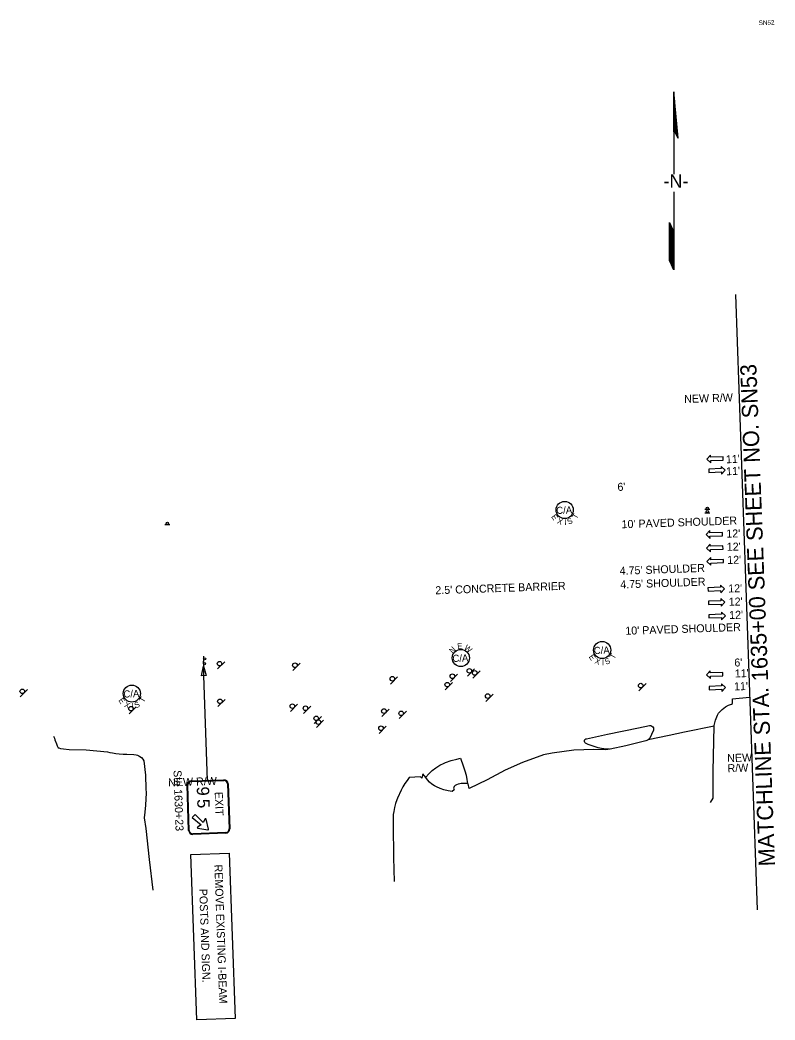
# Model space of a CAD drawing. Extents: x 1808944 to 1810496, y 1189647 to 1190718.
# Drawn here: x 1809835 to 1810496, y 1189721 to 1190596 of the extents above; entities that cross this region are included whole.
import ezdxf

# ---------------------------------------------------------------- set-up
doc = ezdxf.new("R2010")
doc.units = 0
for name, color, linetype in [('RD_EX_Road', 7, 'Continuous'), ('RD_PD_Final_LnLine', 7, 'Continuous'), ('RD_PD_Final_TX', 7, 'Continuous'), ('RD_PD_RW_TX', 7, 'Continuous'), ('RD_SHT_MatchLine', 7, 'Continuous'), ('RD_SHT_TX', 7, 'Continuous'), ('RD_Sketch1', 7, 'Continuous'), ('RD_Sketch10', 7, 'Continuous'), ('RD_Sketch8', 7, 'Continuous'), ('SN_P_Signs', 7, 'Continuous')]:
    doc.layers.add(name, color=color, linetype=linetype)

# ---------------------------------------------------------------- blocks, each defined once
blk = doc.blocks.new('SARRW2')
at = {"layer": 'RD_PD_Final_LnLine'}
blk.add_lwpolyline([(-12, 1.2), (-12, -1.2), (-2.83, -1.2), (-2.83, -2.83), (0, 0), (-2.83, 2.83), (-2.83, 1.2)], close=True, dxfattribs=at)

msp = doc.modelspace()

# ---------------------------------------------------------------- linework, layer by layer
at = {"layer": 'RD_EX_Road'}
for points in [[(1810442.62, 1189977.66), (1810442.64, 1189978.3), (1810443.87, 1189983.17), (1810445.51, 1189987.51), (1810446.58, 1189989.04), (1810449.64, 1189992.5), (1810451.17, 1189993.65), (1810452.54, 1189994.7), (1810455.27, 1189996.17), (1810457.1, 1189996.88), (1810457.92, 1189997.13), (1810458.6, 1189997.63), (1810458.83, 1189998.02), (1810458.65, 1190001.82), (1810473.66, 1190003.13)], [(1810351.07, 1189957.6), (1810348.97, 1189957.54), (1810346.25, 1189957.86), (1810345.56, 1189958), (1810341.05, 1189958.89), (1810336.64, 1189960.16), (1810332.34, 1189961.8), (1810330.14, 1189962.81), (1810329.47, 1189963.43), (1810329.11, 1189964.27), (1810329.14, 1189965.18), (1810329.55, 1189966), (1810330.26, 1189966.57), (1810330.84, 1189966.77), (1810349.43, 1189970.64), (1810376.41, 1189976.27), (1810386.07, 1189978.24), (1810387.15, 1189978.27), (1810388.16, 1189977.91), (1810388.98, 1189977.21), (1810389.5, 1189976.26), (1810389.64, 1189975.19), (1810389.46, 1189974.29), (1810385.99, 1189966.84), (1810384.92, 1189965.82)], [(1810439.35, 1189910.92), (1810441.82, 1189914.89), (1810441.82, 1189938.28), (1810442.62, 1189977.66), (1810416.84, 1189972.42), (1810403.36, 1189969.57), (1810384.91, 1189965.82), (1810383.61, 1189965.13), (1810382.82, 1189964.9), (1810365.42, 1189960.68), (1810351.7, 1189957.62)], [(1809864.47, 1189969.08), (1809865.33, 1189967.42), (1809865.66, 1189965.91), (1809867.01, 1189962.37), (1809867.68, 1189960.69), (1809868.28, 1189959.44), (1809868.64, 1189958.94), (1809869.18, 1189958.73), (1809870.63, 1189958.34), (1809873.18, 1189957.97), (1809878.17, 1189957.45), (1809892.95, 1189957.07), (1809911.79, 1189955.22), (1809913.82, 1189954.81), (1809915.99, 1189954.46), (1809919.13, 1189953.93), (1809921.98, 1189953.48), (1809925.48, 1189953.35), (1809928.56, 1189953.14), (1809934.88, 1189952.99), (1809936.96, 1189952.63), (1809938.09, 1189952.27), (1809939.22, 1189951.71), (1809940.01, 1189951.28), (1809941.45, 1189950.41), (1809942.74, 1189948.86), (1809943.44, 1189947.42), (1809944.99, 1189934.83), (1809945.4, 1189922.89), (1809945.7, 1189919.36), (1809945.12, 1189908.75), (1809944.29, 1189902.53), (1809943.95, 1189897.58), (1809945.27, 1189888.18), (1809948.1, 1189861), (1809951.3, 1189834.39)], [(1810351.7, 1189957.62), (1810347.88, 1189957.19), (1810337.48, 1189957.23), (1810319.88, 1189956.84), (1810301.01, 1189954.22), (1810293.31, 1189952.6), (1810274.9, 1189946.06), (1810259.72, 1189939.2), (1810243.93, 1189930.88), (1810228.37, 1189923.1), (1810227.29, 1189927.42), (1810226.65, 1189927.52)], [(1810190.36, 1189933.03), (1810193.02, 1189936.11), (1810195.97, 1189938.92), (1810199.18, 1189941.43), (1810202.61, 1189943.61), (1810206.24, 1189945.45), (1810207.41, 1189945.95), (1810212.39, 1189947.67), (1810217.49, 1189949.02), (1810220.64, 1189949.64), (1810223.08, 1189942.98), (1810224.45, 1189938.59), (1810225.58, 1189934.85), (1810226.32, 1189931.02), (1810226.65, 1189927.52)], [(1810226.65, 1189927.52), (1810224.01, 1189927.73), (1810221.37, 1189927.54), (1810218.79, 1189926.96), (1810218.57, 1189926.89), (1810217.28, 1189926.58), (1810216.13, 1189925.91), (1810215.22, 1189924.94), (1810214.79, 1189924.15), (1810214.6, 1189923.39), (1810214.8, 1189922.63), (1810215.22, 1189922.14), (1810213.33, 1189920.65), (1810209.74, 1189921.1), (1810206.21, 1189921.94), (1810202.79, 1189923.15), (1810199.52, 1189924.73), (1810197.95, 1189925.66), (1810195.68, 1189927.04), (1810193.63, 1189928.74), (1810191.86, 1189930.72), (1810190.37, 1189932.98), (1810187.61, 1189935.99), (1810186.82, 1189932.14), (1810185.74, 1189933.59), (1810175.86, 1189932.99), (1810173.86, 1189930.31), (1810172.02, 1189927.52), (1810170.34, 1189924.62), (1810168.86, 1189921.67), (1810165.55, 1189914.78), (1810164.93, 1189913.42), (1810163.85, 1189910.06), (1810162.95, 1189906.65), (1810162.25, 1189903.19), (1810161.85, 1189900.48), (1810161.61, 1189891.47), (1810162, 1189862.97), (1810162.47, 1189841.87)]]:
    msp.add_lwpolyline(points, dxfattribs=at)
at = {"layer": 'RD_SHT_MatchLine'}
msp.add_line((1810461.25, 1190355.41), (1810480.22, 1189817.08), dxfattribs=at)
at = {"layer": 'RD_Sketch1'}
for p, q in [((1810407.42, 1190532.83), (1810407.22, 1190497.66)), ((1810411.15, 1190492.12), (1810407.42, 1190532.83)), ((1810407.42, 1190497.96), (1810407.42, 1190476.13)), ((1810407.73, 1190499.07), (1810411.15, 1190492.12)), ((1810407.42, 1190476.13), (1810407.42, 1190460.66)), ((1810407.42, 1190445.21), (1810407.42, 1190419.44)), ((1810403.43, 1190404.38), (1810403.43, 1190418.55)), ((1810403.43, 1190418.55), (1810407.42, 1190409.99)), ((1810407.42, 1190419.44), (1810407.42, 1190376.92)), ((1810403.43, 1190385.48), (1810403.43, 1190404.38)), ((1810407.42, 1190376.92), (1810403.43, 1190385.48))]:
    msp.add_line(p, q, dxfattribs=at)
for points in [[(1810407.44, 1190498.26), (1810407.44, 1190532.7)], [(1810407.53, 1190498.52), (1810407.53, 1190531.67)], [(1810407.62, 1190498.78), (1810407.63, 1190530.64)], [(1810407.72, 1190499.04), (1810407.72, 1190529.61)], [(1810407.81, 1190498.89), (1810407.81, 1190528.57)], [(1810407.91, 1190498.7), (1810407.91, 1190527.54)], [(1810408, 1190498.51), (1810408, 1190526.51)], [(1810407.34, 1190498), (1810407.34, 1190518.79)], [(1810408.1, 1190498.32), (1810408.1, 1190525.48)], [(1810408.19, 1190498.12), (1810408.19, 1190524.44)], [(1810408.29, 1190497.93), (1810408.29, 1190523.41)], [(1810408.38, 1190497.74), (1810408.38, 1190522.38)], [(1810408.48, 1190497.55), (1810408.48, 1190521.35)], [(1810408.57, 1190497.36), (1810408.57, 1190520.31)], [(1810408.66, 1190497.17), (1810408.66, 1190519.28)], [(1810408.76, 1190496.97), (1810408.76, 1190518.25)], [(1810408.85, 1190496.78), (1810408.85, 1190517.22)], [(1810408.95, 1190496.59), (1810408.95, 1190516.18)], [(1810409.04, 1190496.4), (1810409.04, 1190515.15)], [(1810409.14, 1190496.21), (1810409.14, 1190514.12)], [(1810409.23, 1190496.02), (1810409.23, 1190513.09)], [(1810409.33, 1190495.82), (1810409.33, 1190512.05)], [(1810409.42, 1190495.63), (1810409.42, 1190511.02)], [(1810409.51, 1190495.44), (1810409.51, 1190509.99)], [(1810409.61, 1190495.25), (1810409.61, 1190508.96)], [(1810407.25, 1190497.75), (1810407.25, 1190502.89)], [(1810409.7, 1190495.06), (1810409.7, 1190507.92)], [(1810409.8, 1190494.86), (1810409.8, 1190506.89)], [(1810409.89, 1190494.67), (1810409.89, 1190505.86)], [(1810409.99, 1190494.48), (1810409.99, 1190504.83)], [(1810410.08, 1190494.29), (1810410.08, 1190503.79)], [(1810410.18, 1190494.1), (1810410.18, 1190502.76)], [(1810410.27, 1190493.91), (1810410.27, 1190501.73)], [(1810410.37, 1190493.71), (1810410.37, 1190500.7)], [(1810410.46, 1190493.52), (1810410.46, 1190499.66)], [(1810410.55, 1190493.33), (1810410.55, 1190498.63)], [(1810410.65, 1190493.14), (1810410.65, 1190497.6)], [(1810410.74, 1190492.95), (1810410.74, 1190496.57)], [(1810410.84, 1190492.76), (1810410.84, 1190495.53)], [(1810410.93, 1190492.56), (1810410.93, 1190494.5)], [(1810411.03, 1190492.37), (1810411.03, 1190493.47)], [(1810411.12, 1190492.18), (1810411.12, 1190492.44)], [(1810403.51, 1190385.32), (1810403.51, 1190418.39)], [(1810403.6, 1190385.12), (1810403.6, 1190418.19)], [(1810403.7, 1190384.91), (1810403.7, 1190417.98)], [(1810403.79, 1190384.71), (1810403.79, 1190417.78)], [(1810403.89, 1190384.51), (1810403.89, 1190417.58)], [(1810403.98, 1190384.31), (1810403.98, 1190417.38)], [(1810404.08, 1190384.1), (1810404.08, 1190417.17)], [(1810404.17, 1190383.9), (1810404.17, 1190416.97)], [(1810404.26, 1190383.7), (1810404.26, 1190416.77)], [(1810404.36, 1190383.5), (1810404.36, 1190416.57)], [(1810404.45, 1190383.29), (1810404.45, 1190416.36)], [(1810404.55, 1190383.09), (1810404.55, 1190416.16)], [(1810404.64, 1190382.89), (1810404.64, 1190415.96)], [(1810404.74, 1190382.68), (1810404.74, 1190415.76)], [(1810404.83, 1190382.48), (1810404.83, 1190415.55)], [(1810404.93, 1190382.28), (1810404.93, 1190415.35)], [(1810405.02, 1190382.08), (1810405.02, 1190415.15)], [(1810405.11, 1190381.87), (1810405.11, 1190414.94)], [(1810405.21, 1190381.67), (1810405.21, 1190414.74)], [(1810405.3, 1190381.47), (1810405.3, 1190414.54)], [(1810405.4, 1190381.27), (1810405.4, 1190414.34)], [(1810405.49, 1190381.06), (1810405.49, 1190414.13)], [(1810405.59, 1190380.86), (1810405.59, 1190413.93)], [(1810405.68, 1190380.66), (1810405.68, 1190413.73)], [(1810405.78, 1190380.46), (1810405.78, 1190413.53)], [(1810405.87, 1190380.25), (1810405.87, 1190413.32)], [(1810405.97, 1190380.05), (1810405.97, 1190413.12)], [(1810406.06, 1190379.85), (1810406.06, 1190412.92)], [(1810406.15, 1190379.65), (1810406.15, 1190412.72)], [(1810406.25, 1190379.44), (1810406.25, 1190412.51)], [(1810406.34, 1190379.24), (1810406.34, 1190412.31)], [(1810406.44, 1190379.04), (1810406.44, 1190412.11)], [(1810406.53, 1190378.83), (1810406.53, 1190411.91)], [(1810406.63, 1190378.63), (1810406.63, 1190411.7)], [(1810406.72, 1190378.43), (1810406.72, 1190411.5)], [(1810406.82, 1190378.23), (1810406.82, 1190411.3)], [(1810406.91, 1190378.02), (1810406.91, 1190411.09)], [(1810407, 1190377.82), (1810407, 1190410.89)], [(1810407.1, 1190377.62), (1810407.1, 1190410.69)], [(1810407.19, 1190377.42), (1810407.19, 1190410.49)], [(1810407.29, 1190377.21), (1810407.29, 1190410.28)], [(1810407.38, 1190377.01), (1810407.38, 1190410.08)]]:
    msp.add_lwpolyline(points, dxfattribs=at)
at = {"layer": 'RD_Sketch10'}
msp.add_circle((1810220.98, 1190037.46), 7.5, dxfattribs=at)
at = {"layer": 'RD_Sketch8'}
for centre in [(1810311.85, 1190166.94), (1810344.68, 1190044.38), (1809933.05, 1190006.29)]:
    msp.add_circle(centre, 7.5, dxfattribs=at)
at = {"layer": 'SN_P_Signs'}
for p, q in [((1810434.43, 1190167.51), (1810438.93, 1190167.51)), ((1810434.39, 1190164.35), (1810438.89, 1190164.35)), ((1809961.89, 1190154.34), (1809966.39, 1190154.34)), ((1809995.6, 1190038.91), (1809995.76, 1190034.42)), ((1809995.54, 1190034.65), (1809995.7, 1190030.16)), ((1809999.22, 1189930.38), (1809995.7, 1190030.16)), ((1810008.04, 1190027.83), (1810014.4, 1190034.19)), ((1810074.01, 1190026.46), (1810080.37, 1190032.83)), ((1810226.67, 1190021.56), (1810233.04, 1190027.93)), ((1810159.27, 1190014.67), (1810165.64, 1190021.03)), ((1810211.82, 1190016.82), (1810218.18, 1190023.18)), ((1810231.39, 1190019.73), (1810237.75, 1190026.09)), ((1810207.3, 1190009.49), (1810213.67, 1190015.85)), ((1810376.64, 1190008.63), (1810383.01, 1190015)), ((1809835.39, 1190003.59), (1809841.75, 1190009.96)), ((1810242.75, 1189999.49), (1810249.11, 1190005.85)), ((1809930.6, 1189988.47), (1809936.96, 1189994.84)), ((1810008.38, 1189994.87), (1810014.74, 1190001.24)), ((1810071.74, 1189990.62), (1810078.1, 1189996.99)), ((1810083.25, 1189988.84), (1810089.61, 1189995.21)), ((1810151.86, 1189986.34), (1810158.23, 1189992.71)), ((1810092.64, 1189980.01), (1810099, 1189986.38)), ((1810166.99, 1189984.41), (1810173.36, 1189990.77)), ((1810094.55, 1189976.75), (1810100.91, 1189983.11)), ((1810149.35, 1189971.34), (1810155.71, 1189977.71)), ((1809982.74, 1189886.57), (1809981.35, 1189926.14)), ((1809983.34, 1189886.59), (1809981.95, 1189926.16)), ((1809984.82, 1189929.87), (1810013.6, 1189930.88)), ((1809984.84, 1189929.27), (1810013.62, 1189930.28)), ((1810016.73, 1189927.39), (1810018.12, 1189887.82)), ((1810017.32, 1189927.41), (1810018.72, 1189887.84)), ((1810015.23, 1189884.71), (1809986.45, 1189883.7)), ((1810015.25, 1189884.11), (1809986.47, 1189883.1)), ((1809984.67, 1189865.62), (1810018.27, 1189866.8)), ((1809989.78, 1189720.69), (1809984.67, 1189865.62)), ((1810018.27, 1189866.8), (1810023.38, 1189721.87)), ((1810023.38, 1189721.87), (1809989.78, 1189720.69))]:
    msp.add_line(p, q, dxfattribs=at)
msp.add_lwpolyline([(1809993.94, 1190021.89), (1809995.7, 1190030.16), (1809998.04, 1190022.03)], close=True, dxfattribs=at)
for points in [[(1809995.44, 1189893.41), (1809988.4, 1189900.59), (1809985.94, 1189897.96)], [(1809985.94, 1189897.96), (1809993.6, 1189891.43)], [(1809997.23, 1189896.62), (1809995.44, 1189893.41)], [(1810000.12, 1189887.72), (1809998.06, 1189896.51)], [(1809993.6, 1189891.43), (1809990.52, 1189889.43)], [(1809990.7, 1189888.61), (1809999.61, 1189887.17)]]:
    msp.add_lwpolyline(points, dxfattribs=at)
for centre, radius in [((1810436.69, 1190168.53), 1), ((1810436.64, 1190165.36), 1), ((1809964.15, 1190155.36), 1), ((1809996.69, 1190036.69), 1), ((1809996.63, 1190032.43), 1), ((1810009.8, 1190032.45), 2), ((1810075.77, 1190031.09), 2), ((1810228.43, 1190026.19), 2), ((1810161.03, 1190019.29), 2), ((1810213.58, 1190021.44), 2), ((1810233.15, 1190024.35), 2), ((1809837.15, 1190008.22), 2), ((1810209.06, 1190014.11), 2), ((1810378.4, 1190013.26), 2), ((1810010.14, 1189999.5), 2), ((1810244.51, 1190004.11), 2), ((1809932.36, 1189993.1), 2), ((1810073.5, 1189995.25), 2), ((1810085.01, 1189993.47), 2), ((1810153.63, 1189990.97), 2), ((1810094.4, 1189984.64), 2), ((1810168.76, 1189989.03), 2), ((1810096.31, 1189981.37), 2), ((1810151.11, 1189975.97), 2)]:
    msp.add_circle(centre, radius, dxfattribs=at)
for centre, radius, start, end in [((1809984.94, 1189926.27), 3.6, 92.01838, 182.01838), ((1809984.94, 1189926.27), 3, 92.01838, 182.01838), ((1810013.73, 1189927.28), 3.6, 2.01838, 92.01838), ((1810013.73, 1189927.28), 3, 2.01838, 92.01838), ((1809997.62, 1189896.4), 0.45, 13.19628, 150.98048), ((1809990.77, 1189889.05), 0.45, 123.05628, 260.84048), ((1809999.68, 1189887.62), 0.45, 260.84048, 13.19628), ((1810015.12, 1189887.71), 3, 272.01838, 2.01838), ((1810015.12, 1189887.71), 3.6, 272.01838, 2.01838), ((1809986.34, 1189886.7), 3.6, 182.01838, 272.01838), ((1809986.34, 1189886.7), 3, 182.01838, 272.01838)]:
    msp.add_arc(centre, radius, start, end, dxfattribs=at)

# ---------------------------------------------------------------- block references
at = {"layer": 'RD_PD_Final_LnLine', "xscale": 1.1999999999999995, "yscale": 1.2000000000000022}
for p, rotation in [((1810436.21, 1190211.5), -177.9816202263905), ((1810452.33, 1190201.77), 2.018379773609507), ((1810435.55, 1190145.36), -177.9816202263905), ((1810435.96, 1190133.58), -177.9816202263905), ((1810436.38, 1190121.8), -177.9816202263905), ((1810451.63, 1190097.95), 2.018379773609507), ((1810452.04, 1190086.17), 2.018379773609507), ((1810452.46, 1190074.39), 2.018379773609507), ((1810435.89, 1190022.77), -177.9816202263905), ((1810452.65, 1190011.63), 2.018379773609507)]:
    msp.add_blockref('SARRW2', p, dxfattribs=dict(at, rotation=rotation))

# ---------------------------------------------------------------- texts
at = {"layer": 'RD_PD_Final_TX'}
for s, rotation, p in [("11'", 3.01838, (1810453.12, 1190207.73)), ("11'", 3.01838, (1810453.33, 1190197.23)), ("6'", 3.01838, (1810358.17, 1190183.54)), ("10' PAVED SHOULDER", 1.90447, (1810361.72, 1190150.93)), ("12'", 1.39156, (1810453.35, 1190142.72)), ("12'", 1.39156, (1810453.75, 1190131.2)), ("12'", 1.39156, (1810454.16, 1190119.68)), ("4.75' SHOULDER", 2.01838, (1810360.06, 1190110.18)), ("4.75' SHOULDER", 2.01838, (1810360.59, 1190098.19)), ("2.5' CONCRETE BARRIER", 2.02012, (1810198.74, 1190093.15)), ("12'", 1.39156, (1810455.04, 1190094.71)), ("12'", 1.39156, (1810455.45, 1190083.12)), ("12'", 1.39156, (1810455.86, 1190071.53)), ("10' PAVED SHOULDER", 1.90447, (1810365.01, 1190057.72)), ("6'", 2.01838, (1810460.42, 1190029.89)), ("11'", 2.01838, (1810460.81, 1190020.35)), ("11'", 2.01838, (1810460.13, 1190009.01))]:
    msp.add_text(s, height=7, rotation=rotation, dxfattribs=at).set_placement(p)
at = {"layer": 'RD_PD_RW_TX'}
for s, p in [('NEW R/W', (1810416.51, 1190260.56)), ('NEW', (1810454.18, 1189946.3)), ('R/W', (1810454.47, 1189937.43)), ('NEW R/W', (1809964.9, 1189924.99))]:
    msp.add_text(s, height=7, rotation=1.88659, dxfattribs=at).set_placement(p)
at = {"layer": 'RD_SHT_TX'}
for s, height, rotation, p in [('SN52', 4, 2.01838, (1810481.69, 1190591.16)), ('MATCHLINE STA. 1635+00 SEE SHEET NO. SN53', 14.1726, 92.14236, (1810495.97, 1189855.41))]:
    msp.add_text(s, height=height, rotation=rotation, dxfattribs=at).set_placement(p)
at = {"layer": 'RD_Sketch1'}
msp.add_text('-N-', height=11.811, rotation=0, dxfattribs=at).set_placement((1810398.23, 1190448.92))
at = {"layer": 'RD_Sketch10'}
for s, height, rotation, p in [('N', 5, 46.88815, (1810213.73, 1190041.04)), ('E', 5, 6.35143, (1810218.15, 1190045.07)), ('W', 5, 321.321, (1810223.32, 1190045.5)), ('C/A', 6.25, 2.01838, (1810213.69, 1190033.92))]:
    msp.add_text(s, height=height, rotation=rotation, dxfattribs=at).set_placement(p)
at = {"layer": 'RD_Sketch8'}
for s, height, rotation, p in [('C/A', 6.25, 2.01838, (1810304.56, 1190163.41)), ('E', 5, 305.22963, (1810299.83, 1190161)), ('X', 5, 337.659, (1810304.81, 1190155.51)), ('S', 5, 23.81082, (1810315.3, 1190153.98)), ('T', 5, 60.20353, (1810322.34, 1190158.6)), ('I', 5, 1.819, (1810311.66, 1190153.68)), ('C/A', 6.25, 2.01838, (1810337.39, 1190040.84)), ('E', 5, 305.22963, (1810332.66, 1190038.43)), ('X', 5, 337.659, (1810337.64, 1190032.95)), ('S', 5, 23.81082, (1810348.13, 1190031.42)), ('T', 5, 60.20353, (1810355.17, 1190036.04)), ('I', 5, 1.819, (1810344.49, 1190031.12)), ('E', 5, 305.22963, (1809921.03, 1190000.34)), ('C/A', 6.25, 2.01838, (1809925.76, 1190002.75)), ('T', 5, 60.20353, (1809943.54, 1189997.94)), ('X', 5, 337.659, (1809926.01, 1189994.86)), ('I', 5, 1.819, (1809932.86, 1189993.02)), ('S', 5, 23.81082, (1809936.5, 1189993.33))]:
    msp.add_text(s, height=height, rotation=rotation, dxfattribs=at).set_placement(p)
at = {"layer": 'SN_P_Signs'}
for s, height, rotation, p in [('Sta 1630+23', 7, 272.01846, (1809969.46, 1189939.17)), ('9', 10.8, 272.01838, (1809989.8, 1189924.77)), ('EXIT', 7, 272.01838, (1810005.57, 1189920.19)), ('5', 10.8, 272.01838, (1809990.19, 1189913.85)), ('REMOVE EXISTING I-BEAM', 6.9998, 272.01846, (1810005.26, 1189856.59)), ('POSTS AND SIGN.', 6.9998, 272.01846, (1809992, 1189835.4))]:
    msp.add_text(s, height=height, rotation=rotation, dxfattribs=at).set_placement(p)

doc.saveas('drawing.dxf')
